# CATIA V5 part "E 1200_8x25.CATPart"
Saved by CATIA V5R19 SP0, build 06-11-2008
Nomenclature: E 1200_8x25
Description: PART-E 1200_8x25-DESC
Property "Hersteller": "Meusburger"
Property "Material": "12.9 ISO 4762 (DIN 912)"
Property "Bestellnummer": "E 1200/8x25"
Property "Teilenummer": "E 1200/8x25"
Property "Beschreibung": "Zylinderkopfschraube mit Innensechskant _ Cylinder head screw with hexagon socket"
Material "Steel": density 7860 kg/m3, Young's modulus 2e+11 Pa, Poisson ratio 0.266, thermal expansion 1.17e-05 1/K
Bounding box of the stored display mesh (mm): x -6.5 to 6.5, y -6.49 to 6.49, z -25 to 8
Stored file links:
  G:\UTB\Kombinované\Bakalářská práce\Catia\FORMA\E 1200_8x25.CATPart
  D:\Aplikace\CATIA\Nová složka\win_b64\startup\materials\Catalog.CATMaterial
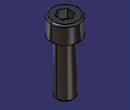
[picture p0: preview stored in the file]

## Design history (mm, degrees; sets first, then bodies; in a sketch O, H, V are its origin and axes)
Body1 "E 1200_8x25" (main body)
  Solid1: solid without history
